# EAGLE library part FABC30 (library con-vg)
Female Connector C/3, 30 Solder DIN EN 60 603-02 Source: www.erni.com .. 254891.pdf
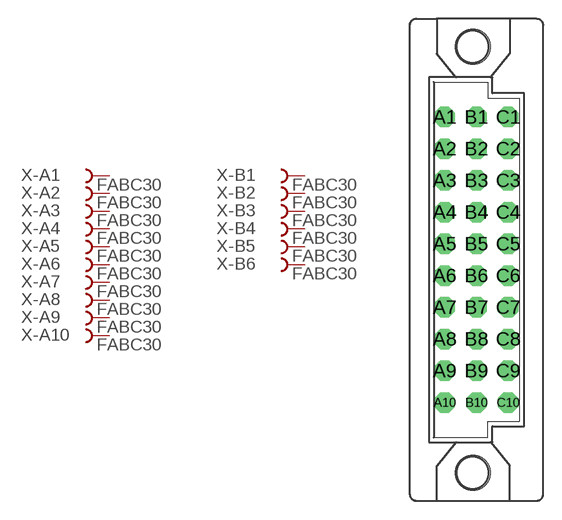
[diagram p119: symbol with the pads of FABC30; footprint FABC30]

Designator prefix X; gates -A1=F -A2=F -A3=F -A4=F -A5=F -A6=F -A7=F -A8=F -A9=F -A10=F -B1=F -B2=F -B3=F -B4=F -B5=F -B6=F -B7=F -B8=F -B9=F -B10=F -C1=F -C2=F -C3=F -C4=F -C5=F -C6=F -C7=F -C8=F -C9=F -C10=F

## FABC30  [FABC30]
A1  -A1:B  pas
A2  -A2:B  pas
A3  -A3:B  pas
A4  -A4:B  pas
A5  -A5:B  pas
A6  -A6:B  pas
A7  -A7:B  pas
A8  -A8:B  pas
A9  -A9:B  pas
A10  -A10:B  pas
B1  -B1:B  pas
B2  -B2:B  pas
B3  -B3:B  pas
B4  -B4:B  pas
B5  -B5:B  pas
B6  -B6:B  pas
B7  -B7:B  pas
B8  -B8:B  pas
B9  -B9:B  pas
B10  -B10:B  pas
C1  -C1:B  pas
C2  -C2:B  pas
C3  -C3:B  pas
C4  -C4:B  pas
C5  -C5:B  pas
C6  -C6:B  pas
C7  -C7:B  pas
C8  -C8:B  pas
C9  -C9:B  pas
C10  -C10:B  pas

## Footprint FABC30 (pad centres in mm)
Female Connector C/3, 30 Solder DIN EN 60 603-02 Source: www.erni.com .. 254891.pdf
drill 1.1 pad 1.6 octagon: A1 -2.54,11.43; A2 -2.54,8.89; A3 -2.54,6.35; A4 -2.54,3.81; A5 -2.54,1.27; A6 -2.54,-1.27; A7 -2.54,-3.81; A8 -2.54,-6.35; A9 -2.54,-8.89; A10 -2.54,-11.43; B1 0,11.43; B2 0,8.89; B3 0,6.35; B4 0,3.81; B5 0,1.27; B6 0,-1.27; B7 0,-3.81; B8 0,-6.35; B9 0,-8.89; B10 0,-11.43; C1 2.54,11.43; C2 2.54,8.89; C3 2.54,6.35; C4 2.54,3.81; C5 2.54,1.27; C6 2.54,-1.27; C7 2.54,-3.81; C8 2.54,-6.35; C9 2.54,-8.89; C10 2.54,-11.43
hole 2.794 at -0.305,17.069
hole 2.794 at -0.305,-17.069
